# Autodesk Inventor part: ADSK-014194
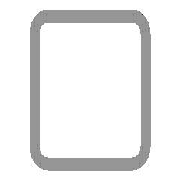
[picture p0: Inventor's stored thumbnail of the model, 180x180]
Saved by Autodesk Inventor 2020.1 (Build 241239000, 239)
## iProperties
Created: 2019-01
Part Number: ADSK-014194
Material: Stahl, weich
Description: Rohrleitung
Document SubType Name: Modeling
Standard: DIN
Designer: lutzd
Standard Revision: 2006-07
Standards Organization: DIN
Language: de-DE
Size Designation: 50 x 50 x 5
Categories: <MemberInstance><Categories><Category DisplayName="Profile" InternalName="089c4875-fa83-4c05-b084-43b9cc11f5ed" Mnemonic="GRDR"><CategoryParameter DisplayName="
Stock Number: 50 x 50 x 5
Mass: 2226.55 g
Surface Area: 1128.25 cm^2
Volume: 283.636 cm^3
Density: 7.85 g/cm^3
Appearance: Halbpoliert
_CCFamilyMember: 16
_CCFamilyDisplayName: DIN EN 10210-2 (USAS B17.1 quadratisch) - Rohrleitung — In Klammern angegebene Größen wurden aufgehoben
_FrameMemberDoc: Frame Member File
_Version: 15.0.0
_GetPNFromCC: 1
IsCustomPart: 1
G_L: 330,000 mm
G_W: 50,000 mm
G_H: 50,000 mm
DocNumber: ADSK-014174
Folder: .
Dimensions: 50x50x330 mm
Mass: 2,227 kg
Title: Profil-Bauteil
Author: lutzd
Revision Number: -
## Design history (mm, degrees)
node "Startebene"
node "Endebene"
sketch "Skizze"
  geometry: L1 (-25, -17.5)-(-25, 17.5); L2 (-17.5, 25)-(17.5, 25); L3 (25, 17.5)-(25, -17.5); L4 (17.5, -25)-(-17.5, -25); L5 (-15, 20)-(15, 20); L6 (20, 15)-(20, -15); L7 (15, -20)-(-15, -20); L8 (-20, -15)-(-20, 15); L9 (0, 37.175)-(0, -37.175) reference; L10 (-37.175, 0)-(37.175, 0) reference; A1 r 7.5 centre (-17.5, -17.5) between (-25, -17.5) and (-17.5, -25); A2 r 7.5 centre (-17.5, 17.5) between (-17.5, 25) and (-25, 17.5); A3 r 7.5 centre (17.5, 17.5) between (25, 17.5) and (17.5, 25); A4 r 7.5 centre (17.5, -17.5) between (17.5, -25) and (25, -17.5); A5 r 5 centre (-15, -15) between (-20, -15) and (-15, -20); A6 r 5 centre (-15, 15) between (-15, 20) and (-20, 15); A7 r 5 centre (15, 15) between (20, 15) and (15, 20); A8 r 5 centre (15, -15) between (15, -20) and (20, -15)
  constraints: 16 end point, 16 point on circle, 16 tangent, 8 centre point, 6 equal radius, 4 parallel, 2 perpendicular, 2 other
  dimensions: "d7" = 7.5 radius of A1 (= G_IR); "d10" = 50 distance between parallel lines of L2 L4 (= G_H); "d11" = 50 distance between parallel lines of L1 L3 (= G_W); "d12" = 5 distance between parallel lines of L3 L6 (= G_T); "d15" = 25 distance between parallel lines of L2 L10 (= 0.5 x d10); "d16" = 25 distance between parallel lines of L9 L3 (= 0.5 x d11); "d19" = 5 radius of A5 (= G_T); "d20" = 5 distance between parallel lines of L4 L7 (= G_T)
extrude "Körper" new body sketch "Skizze" stored distance "d3" = 330 (= G_L); taper "d4" = 0 deg
node "Driven Length"
  sketch "Sketch3"
    geometry: L1 (0, 0)-(10, 0) reference
    constraints: 2 end point, 1 horizontal
  workplane "Work Plane3"
  sketch "Sketch4"
    geometry: L1 (-2, 25)-(12, 25) reference; L2 (-2, 355)-(12, 355) reference
    dimensions: "d18" = 330 distance between parallel lines of L1 L2 (derived)
workplane "Arbeitsebene4"
feature "Trennen1"
sketch "Skizze5"
  geometry: L1 (0, 35)-(0, 0) reference; L2 (18.5, 34)-(51.5, 34); L3 (51.5, 34)-(51.5, 1); L4 (51.5, 1)-(18.5, 1); L5 (18.5, 1)-(18.5, 34); 8 further points
  constraints: 8 end point, 4 midpoint, 2 coincident, 2 horizontal alignment, 2 parallel, 1 horizontal, 1 perpendicular, 1 vertical alignment
  dimensions: "d21" = 33 distance of L2.start L2.end; "d22" = 33 distance of L2.end L3.end; "d37" = 35 distance from line of L1 point (35, 17.5)
hole "Bohrung1" sketch "Skizze5" diameter "d23" = 22; stored, may be unused: countersink angle "d27" = 90 deg, drill point angle "d29" = 118 deg; dims "d24" = 6, "d25" = 4, "d26" = 2, "d28" = 8
hole "Bohrung2" sketch "Skizze5" diameter "d30" = 6.4; stored, may be unused: countersink angle "d34" = 90 deg, drill point angle "d36" = 118 deg; dims "d31" = 6, "d32" = 4, "d33" = 2, "d35" = 8
body "Solid1"
other parameters: "G_W" = 50 [user parameter; used in 1 equation term], "G_H" = 50 [user parameter; used in 1 equation term], "G_T" = 5 [user parameter; used in 3 equation terms], "G_IR" = 7.5 [user parameter; used in 1 equation term], "G_L" = 330 (= d18) [user parameter; used in 1 equation term], "G_OFFSET_START" = -25 [user parameter; used in 1 equation term], "G_OFFSET_END" = 0 [user parameter; used in 1 equation term], "d13" = 25 (= -G_OFFSET_START), "d14" = 355 (= G_OFFSET_END + B_L), "B_L" = 355 [user parameter; used in 1 equation term], "d17" = 90 deg
